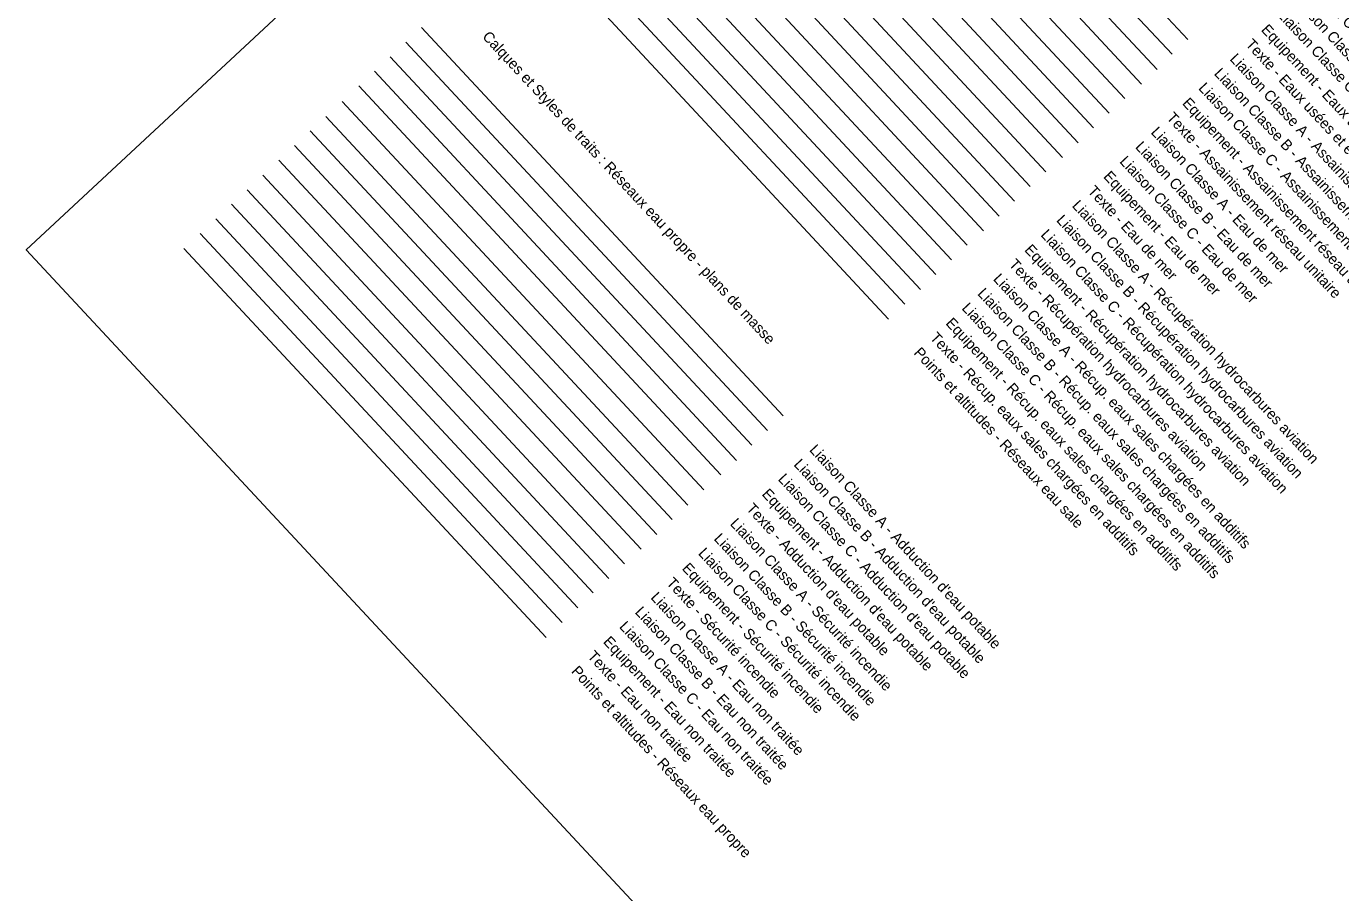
# Model space of a CAD drawing. Extents: x 704383 to 706615, y 7057567 to 7059313.
# Drawn here: x 706317.1 to 706378.5, y 7057628.3 to 7057668.7 of the extents above; entities that cross this region are included whole.
import ezdxf

# ---------------------------------------------------------------- set-up
doc = ezdxf.new("R2010")
doc.units = 0
for name, color, linetype in [('DH_CADRE -CARTOUCHE', 7, 'Continuous'), ('R_EPR_AEP_CANALISATION_CL_A', 7, 'Continuous'), ('R_EPR_AEP_CANALISATION_CL_B', 7, 'Continuous'), ('R_EPR_AEP_CANALISATION_CL_C', 7, 'Continuous'), ('R_EPR_AEP_EQUIP', 7, 'Continuous'), ('R_EPR_AEP_TEXTE', 7, 'Continuous'), ('R_EPR_EAU_NON_TRAITEE_CANALISATION_CL_A', 7, 'Continuous'), ('R_EPR_EAU_NON_TRAITEE_CANALISATION_CL_B', 7, 'Continuous'), ('R_EPR_EAU_NON_TRAITEE_CANALISATION_CL_C', 7, 'Continuous'), ('R_EPR_EAU_NON_TRAITEE_EQUIP', 7, 'Continuous'), ('R_EPR_EAU_NON_TRAITEE_TEXTE', 7, 'Continuous'), ('R_EPR_EAU_PROPRE_ALT_POINT', 7, 'Continuous'), ('R_EPR_INCENDIE_CANALISATION_CL_A', 7, 'Continuous'), ('R_EPR_INCENDIE_CANALISATION_CL_B', 7, 'Continuous'), ('R_EPR_INCENDIE_CANALISATION_CL_C', 7, 'Continuous'), ('R_EPR_INCENDIE_EQUIP', 7, 'Continuous'), ('R_EPR_INCENDIE_TEXTE', 7, 'Continuous'), ('R_ES_EAU_SALE_ALT_POINT', 7, 'Continuous'), ('R_ES_EU_CANALISATION_CL_A', 7, 'Continuous'), ('R_ES_EU_CANALISATION_CL_B', 7, 'Continuous'), ('R_ES_EU_CANALISATION_CL_C', 7, 'Continuous'), ('R_ES_EU_EQUIP', 7, 'Continuous'), ('R_ES_EU_TEXTE', 7, 'Continuous'), ('R_ES_HYDROCARB_CANA_CL_A', 7, 'Continuous'), ('R_ES_HYDROCARB_CANA_CL_B', 7, 'Continuous'), ('R_ES_HYDROCARB_CANA_CL_C', 7, 'Continuous'), ('R_ES_HYDROCARB_EQUIP', 7, 'Continuous'), ('R_ES_HYDROCARB_TEXTE', 7, 'Continuous'), ('R_ES_INCENDIE_CANA_CL_A', 7, 'Continuous'), ('R_ES_INCENDIE_CANA_CL_B', 7, 'Continuous'), ('R_ES_INCENDIE_CANA_CL_C', 7, 'Continuous'), ('R_ES_INCENDIE_EQUIP', 7, 'Continuous'), ('R_ES_INCENDIE_TEXTE', 7, 'Continuous'), ('R_ES_MER_CANALISATION_CL_A', 7, 'Continuous'), ('R_ES_MER_CANALISATION_CL_B', 7, 'Continuous'), ('R_ES_MER_CANALISATION_CL_C', 7, 'Continuous'), ('R_ES_MER_EQUIP', 7, 'Continuous'), ('R_ES_MER_TEXTE', 7, 'Continuous'), ('R_ES_UNITAIRE_CANALISATION_CL_A', 7, 'Continuous'), ('R_ES_UNITAIRE_CANALISATION_CL_B', 7, 'Continuous'), ('R_ES_UNITAIRE_CANALISATION_CL_C', 7, 'Continuous'), ('R_ES_UNITAIRE_EQUIP', 7, 'Continuous'), ('R_ES_UNITAIRE_TEXTE', 7, 'Continuous')]:
    doc.layers.add(name, color=color, linetype=linetype)

msp = doc.modelspace()

# ---------------------------------------------------------------- linework, layer by layer
at = {"layer": 'DH_CADRE -CARTOUCHE'}
msp.add_lwpolyline([(706481.837, 7057811.547), (706566.98, 7057720.028), (706402.247, 7057566.771), (706317.104, 7057658.289)], close=True, dxfattribs=at)
at = {"layer": 'R_EPR_AEP_CANALISATION_CL_A'}
msp.add_line((706335.56, 7057668.671), (706352.442, 7057650.524), dxfattribs=at)
at = {"layer": 'R_EPR_AEP_CANALISATION_CL_B'}
msp.add_line((706334.828, 7057667.99), (706351.71, 7057649.843), dxfattribs=at)
at = {"layer": 'R_EPR_AEP_CANALISATION_CL_C'}
msp.add_line((706334.096, 7057667.309), (706350.978, 7057649.162), dxfattribs=at)
at = {"layer": 'R_EPR_AEP_EQUIP'}
msp.add_line((706333.364, 7057666.628), (706350.276, 7057648.449), dxfattribs=at)
at = {"layer": 'R_EPR_AEP_TEXTE'}
msp.add_line((706332.631, 7057665.946), (706349.544, 7057647.768), dxfattribs=at)
at = {"layer": 'R_EPR_EAU_NON_TRAITEE_CANALISATION_CL_A'}
msp.add_line((706328.148, 7057661.775), (706345.04, 7057643.618), dxfattribs=at)
at = {"layer": 'R_EPR_EAU_NON_TRAITEE_CANALISATION_CL_B'}
msp.add_line((706327.416, 7057661.094), (706344.308, 7057642.937), dxfattribs=at)
at = {"layer": 'R_EPR_EAU_NON_TRAITEE_CANALISATION_CL_C'}
msp.add_line((706326.683, 7057660.413), (706343.576, 7057642.255), dxfattribs=at)
at = {"layer": 'R_EPR_EAU_NON_TRAITEE_EQUIP'}
msp.add_line((706325.951, 7057659.732), (706342.864, 7057641.553), dxfattribs=at)
at = {"layer": 'R_EPR_EAU_NON_TRAITEE_TEXTE'}
msp.add_line((706325.219, 7057659.05), (706342.132, 7057640.872), dxfattribs=at)
at = {"layer": 'R_EPR_EAU_PROPRE_ALT_POINT'}
msp.add_line((706324.464, 7057658.348), (706341.377, 7057640.169), dxfattribs=at)
at = {"layer": 'R_EPR_INCENDIE_CANALISATION_CL_A'}
msp.add_line((706331.854, 7057665.223), (706348.746, 7057647.066), dxfattribs=at)
at = {"layer": 'R_EPR_INCENDIE_CANALISATION_CL_B'}
msp.add_line((706331.099, 7057664.521), (706347.991, 7057646.363), dxfattribs=at)
at = {"layer": 'R_EPR_INCENDIE_CANALISATION_CL_C'}
msp.add_line((706330.367, 7057663.84), (706347.259, 7057645.682), dxfattribs=at)
at = {"layer": 'R_EPR_INCENDIE_EQUIP'}
msp.add_line((706329.635, 7057663.158), (706346.547, 7057644.98), dxfattribs=at)
at = {"layer": 'R_EPR_INCENDIE_TEXTE'}
msp.add_line((706328.903, 7057662.477), (706345.815, 7057644.298), dxfattribs=at)
at = {"layer": 'R_ES_EAU_SALE_ALT_POINT'}
msp.add_line((706340.458, 7057673.228), (706357.37, 7057655.049), dxfattribs=at)
at = {"layer": 'R_ES_HYDROCARB_CANA_CL_A'}
msp.add_line((706347.825, 7057680.081), (706364.717, 7057661.924), dxfattribs=at)
at = {"layer": 'R_ES_HYDROCARB_CANA_CL_B'}
msp.add_line((706347.093, 7057679.4), (706363.985, 7057661.243), dxfattribs=at)
at = {"layer": 'R_ES_HYDROCARB_CANA_CL_C'}
msp.add_line((706346.361, 7057678.719), (706363.253, 7057660.562), dxfattribs=at)
at = {"layer": 'R_ES_HYDROCARB_EQUIP'}
msp.add_line((706345.628, 7057678.038), (706362.541, 7057659.859), dxfattribs=at)
at = {"layer": 'R_ES_HYDROCARB_TEXTE'}
msp.add_line((706344.896, 7057677.357), (706361.809, 7057659.178), dxfattribs=at)
at = {"layer": 'R_ES_INCENDIE_CANA_CL_A'}
msp.add_line((706344.141, 7057676.655), (706361.034, 7057658.497), dxfattribs=at)
at = {"layer": 'R_ES_INCENDIE_CANA_CL_B'}
msp.add_line((706343.409, 7057675.973), (706360.302, 7057657.816), dxfattribs=at)
at = {"layer": 'R_ES_INCENDIE_CANA_CL_C'}
msp.add_line((706342.677, 7057675.292), (706359.57, 7057657.135), dxfattribs=at)
at = {"layer": 'R_ES_INCENDIE_EQUIP'}
msp.add_line((706341.945, 7057674.611), (706358.857, 7057656.432), dxfattribs=at)
at = {"layer": 'R_ES_INCENDIE_TEXTE'}
msp.add_line((706341.213, 7057673.93), (706358.125, 7057655.751), dxfattribs=at)
at = {"layer": 'R_ES_MER_CANALISATION_CL_A'}
msp.add_line((706351.508, 7057683.508), (706368.401, 7057665.351), dxfattribs=at)
at = {"layer": 'R_ES_MER_CANALISATION_CL_B'}
msp.add_line((706350.776, 7057682.827), (706367.669, 7057664.67), dxfattribs=at)
at = {"layer": 'R_ES_MER_CANALISATION_CL_C'}
msp.add_line((706350.044, 7057682.146), (706366.936, 7057663.989), dxfattribs=at)
at = {"layer": 'R_ES_MER_EQUIP'}
msp.add_line((706349.312, 7057681.465), (706366.224, 7057663.286), dxfattribs=at)
at = {"layer": 'R_ES_MER_TEXTE'}
msp.add_line((706348.58, 7057680.784), (706365.492, 7057662.605), dxfattribs=at)
at = {"layer": 'R_ES_UNITAIRE_CANALISATION_CL_B'}
msp.add_line((706354.46, 7057686.254), (706371.342, 7057668.107), dxfattribs=at)
at = {"layer": 'R_ES_UNITAIRE_CANALISATION_CL_C'}
msp.add_line((706353.727, 7057685.573), (706370.61, 7057667.426), dxfattribs=at)
at = {"layer": 'R_ES_UNITAIRE_EQUIP'}
msp.add_line((706352.995, 7057684.892), (706369.908, 7057666.713), dxfattribs=at)
at = {"layer": 'R_ES_UNITAIRE_TEXTE'}
msp.add_line((706352.263, 7057684.211), (706369.176, 7057666.032), dxfattribs=at)

# ---------------------------------------------------------------- texts
at = {"layer": 'DH_CADRE -CARTOUCHE'}
msp.add_text(' Calques et Styles de traits : Réseaux eau propre - plans de masse', height=0.5, rotation=312.93319, dxfattribs=at).set_placement((706338.244, 7057668.355))
at = {"layer": 'R_EPR_AEP_CANALISATION_CL_A'}
msp.add_text("Liaison Classe A - Adduction d'eau potable ", height=0.5, rotation=312.93319, dxfattribs=at).set_placement((706353.643, 7057648.913))
at = {"layer": 'R_EPR_AEP_CANALISATION_CL_B'}
msp.add_text("Liaison Classe B - Adduction d'eau potable ", height=0.5, rotation=312.93319, dxfattribs=at).set_placement((706352.911, 7057648.232))
at = {"layer": 'R_EPR_AEP_CANALISATION_CL_C'}
msp.add_text("Liaison Classe C - Adduction d'eau potable ", height=0.5, rotation=312.93319, dxfattribs=at).set_placement((706352.178, 7057647.55))
at = {"layer": 'R_EPR_AEP_EQUIP'}
msp.add_text("Equipement - Adduction d'eau potable ", height=0.5, rotation=312.93319, dxfattribs=at).set_placement((706351.424, 7057646.848))
at = {"layer": 'R_EPR_AEP_TEXTE'}
msp.add_text("Texte - Adduction d'eau potable ", height=0.5, rotation=312.93319, dxfattribs=at).set_placement((706350.691, 7057646.167))
at = {"layer": 'R_EPR_EAU_NON_TRAITEE_CANALISATION_CL_A'}
msp.add_text('Liaison Classe A - Eau non traitée', height=0.5, rotation=312.93319, dxfattribs=at).set_placement((706346.23, 7057642.017))
at = {"layer": 'R_EPR_EAU_NON_TRAITEE_CANALISATION_CL_B'}
msp.add_text('Liaison Classe B - Eau non traitée', height=0.5, rotation=312.93319, dxfattribs=at).set_placement((706345.498, 7057641.336))
at = {"layer": 'R_EPR_EAU_NON_TRAITEE_CANALISATION_CL_C'}
msp.add_text('Liaison Classe C - Eau non traitée', height=0.5, rotation=312.93319, dxfattribs=at).set_placement((706344.766, 7057640.655))
at = {"layer": 'R_EPR_EAU_NON_TRAITEE_EQUIP'}
msp.add_text('Equipement - Eau non traitée', height=0.5, rotation=312.93319, dxfattribs=at).set_placement((706344.011, 7057639.952))
at = {"layer": 'R_EPR_EAU_NON_TRAITEE_TEXTE'}
msp.add_text('Texte - Eau non traitée', height=0.5, rotation=312.93319, dxfattribs=at).set_placement((706343.279, 7057639.271))
at = {"layer": 'R_EPR_EAU_PROPRE_ALT_POINT'}
msp.add_text('Points et altitudes - Réseaux eau propre', height=0.5, rotation=312.93319, dxfattribs=at).set_placement((706342.524, 7057638.569))
at = {"layer": 'R_EPR_INCENDIE_CANALISATION_CL_A'}
msp.add_text('Liaison Classe A - Sécurité incendie', height=0.5, rotation=312.93319, dxfattribs=at).set_placement((706349.937, 7057645.465))
at = {"layer": 'R_EPR_INCENDIE_CANALISATION_CL_B'}
msp.add_text('Liaison Classe B - Sécurité incendie', height=0.5, rotation=312.93319, dxfattribs=at).set_placement((706349.182, 7057644.763))
at = {"layer": 'R_EPR_INCENDIE_CANALISATION_CL_C'}
msp.add_text('Liaison Classe C - Sécurité incendie', height=0.5, rotation=312.93319, dxfattribs=at).set_placement((706348.45, 7057644.081))
at = {"layer": 'R_EPR_INCENDIE_EQUIP'}
msp.add_text('Equipement - Sécurité incendie', height=0.5, rotation=312.93319, dxfattribs=at).set_placement((706347.695, 7057643.379))
at = {"layer": 'R_EPR_INCENDIE_TEXTE'}
msp.add_text('Texte - Sécurité incendie', height=0.5, rotation=312.93319, dxfattribs=at).set_placement((706346.963, 7057642.698))
at = {"layer": 'R_ES_EAU_SALE_ALT_POINT'}
msp.add_text('Points et altitudes - Réseaux eau sale', height=0.5, rotation=312.93319, dxfattribs=at).set_placement((706358.518, 7057653.448))
at = {"layer": 'R_ES_EU_CANALISATION_CL_A'}
msp.add_text('Liaison Classe A - Eaux usées et eaux vannes', height=0.5, rotation=312.93319, dxfattribs=at).set_placement((706376.958, 7057670.604))
at = {"layer": 'R_ES_EU_CANALISATION_CL_B'}
msp.add_text('Liaison Classe B - Eaux usées et eaux vannes', height=0.5, rotation=312.93319, dxfattribs=at).set_placement((706376.226, 7057669.923))
at = {"layer": 'R_ES_EU_CANALISATION_CL_C'}
msp.add_text('Liaison Classe C - Eaux usées et eaux vannes', height=0.5, rotation=312.93319, dxfattribs=at).set_placement((706375.494, 7057669.241))
at = {"layer": 'R_ES_EU_EQUIP'}
msp.add_text('Equipement - Eaux usées et eaux vannes', height=0.5, rotation=312.93319, dxfattribs=at).set_placement((706374.739, 7057668.539))
at = {"layer": 'R_ES_EU_TEXTE'}
msp.add_text('Texte - Eaux usées et eaux vannes', height=0.5, rotation=312.93319, dxfattribs=at).set_placement((706374.007, 7057667.858))
at = {"layer": 'R_ES_HYDROCARB_CANA_CL_A'}
msp.add_text('Liaison Classe A - Récupération hydrocarbures aviation', height=0.5, rotation=312.93319, dxfattribs=at).set_placement((706365.908, 7057660.323))
at = {"layer": 'R_ES_HYDROCARB_CANA_CL_B'}
msp.add_text('Liaison Classe B - Récupération hydrocarbures aviation', height=0.5, rotation=312.93319, dxfattribs=at).set_placement((706365.175, 7057659.642))
at = {"layer": 'R_ES_HYDROCARB_CANA_CL_C'}
msp.add_text('Liaison Classe C - Récupération hydrocarbures aviation', height=0.5, rotation=312.93319, dxfattribs=at).set_placement((706364.443, 7057658.961))
at = {"layer": 'R_ES_HYDROCARB_EQUIP'}
msp.add_text('Equipement - Récupération hydrocarbures aviation', height=0.5, rotation=312.93319, dxfattribs=at).set_placement((706363.688, 7057658.259))
at = {"layer": 'R_ES_HYDROCARB_TEXTE'}
msp.add_text('Texte - Récupération hydrocarbures aviation', height=0.5, rotation=312.93319, dxfattribs=at).set_placement((706362.956, 7057657.578))
at = {"layer": 'R_ES_INCENDIE_CANA_CL_A'}
msp.add_text('Liaison Classe A - Récup. eaux sales chargées en additifs', height=0.5, rotation=312.93319, dxfattribs=at).set_placement((706362.224, 7057656.896))
at = {"layer": 'R_ES_INCENDIE_CANA_CL_B'}
msp.add_text('Liaison Classe B - Récup. eaux sales chargées en additifs', height=0.5, rotation=312.93319, dxfattribs=at).set_placement((706361.492, 7057656.215))
at = {"layer": 'R_ES_INCENDIE_CANA_CL_C'}
msp.add_text('Liaison Classe C - Récup. eaux sales chargées en additifs', height=0.5, rotation=312.93319, dxfattribs=at).set_placement((706360.76, 7057655.534))
at = {"layer": 'R_ES_INCENDIE_EQUIP'}
msp.add_text('Equipement - Récup. eaux sales chargées en additifs', height=0.5, rotation=312.93319, dxfattribs=at).set_placement((706360.005, 7057654.832))
at = {"layer": 'R_ES_INCENDIE_TEXTE'}
msp.add_text('Texte - Récup. eaux sales chargées en additifs', height=0.5, rotation=312.93319, dxfattribs=at).set_placement((706359.273, 7057654.151))
at = {"layer": 'R_ES_MER_CANALISATION_CL_A'}
msp.add_text('Liaison Classe A - Eau de mer', height=0.5, rotation=312.93319, dxfattribs=at).set_placement((706369.591, 7057663.75))
at = {"layer": 'R_ES_MER_CANALISATION_CL_B'}
msp.add_text('Liaison Classe B - Eau de mer', height=0.5, rotation=312.93319, dxfattribs=at).set_placement((706368.859, 7057663.069))
at = {"layer": 'R_ES_MER_CANALISATION_CL_C'}
msp.add_text('Liaison Classe C - Eau de mer', height=0.5, rotation=312.93319, dxfattribs=at).set_placement((706368.127, 7057662.388))
at = {"layer": 'R_ES_MER_EQUIP'}
msp.add_text('Equipement - Eau de mer', height=0.5, rotation=312.93319, dxfattribs=at).set_placement((706367.372, 7057661.686))
at = {"layer": 'R_ES_MER_TEXTE'}
msp.add_text('Texte - Eau de mer', height=0.5, rotation=312.93319, dxfattribs=at).set_placement((706366.64, 7057661.004))
at = {"layer": 'R_ES_UNITAIRE_CANALISATION_CL_A'}
msp.add_text('Liaison Classe A - Assainissement réseau unitaire', height=0.5, rotation=312.93319, dxfattribs=at).set_placement((706373.274, 7057667.177))
at = {"layer": 'R_ES_UNITAIRE_CANALISATION_CL_B'}
msp.add_text('Liaison Classe B - Assainissement réseau unitaire', height=0.5, rotation=312.93319, dxfattribs=at).set_placement((706372.542, 7057666.496))
at = {"layer": 'R_ES_UNITAIRE_CANALISATION_CL_C'}
msp.add_text('Liaison Classe C - Assainissement réseau unitaire', height=0.5, rotation=312.93319, dxfattribs=at).set_placement((706371.81, 7057665.815))
at = {"layer": 'R_ES_UNITAIRE_EQUIP'}
msp.add_text('Equipement - Assainissement réseau unitaire', height=0.5, rotation=312.93319, dxfattribs=at).set_placement((706371.055, 7057665.112))
at = {"layer": 'R_ES_UNITAIRE_TEXTE'}
msp.add_text('Texte - Assainissement réseau unitaire', height=0.5, rotation=312.93319, dxfattribs=at).set_placement((706370.323, 7057664.431))

doc.saveas('drawing.dxf')
